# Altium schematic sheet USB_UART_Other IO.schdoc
size 297 x 209 mm; Border: 1; Width: 1170; Height: 825; Region Start: 1; X Region Count: 6; Y Region Count: 4; Blade Width: 10; Title Block Position: 3; Symbol: Sheet-Symbol_A4; Company: 嘉立创EDA; Version: V1.0; Page Size: A4; @Project Name: New Project_2025-01-23_00-40-50; @Page Count: 4; @Update Date: 2025-08-15; @Create Date: 2025-07-30; @Schematic Name: Schematic3_7; @Page No: 1; @Page Name: 继电器板子; Device: Sheet-Symbol_A4; @Board Name: cm4; @Create Time: 15:34:35; @Update Time: 00:10:44
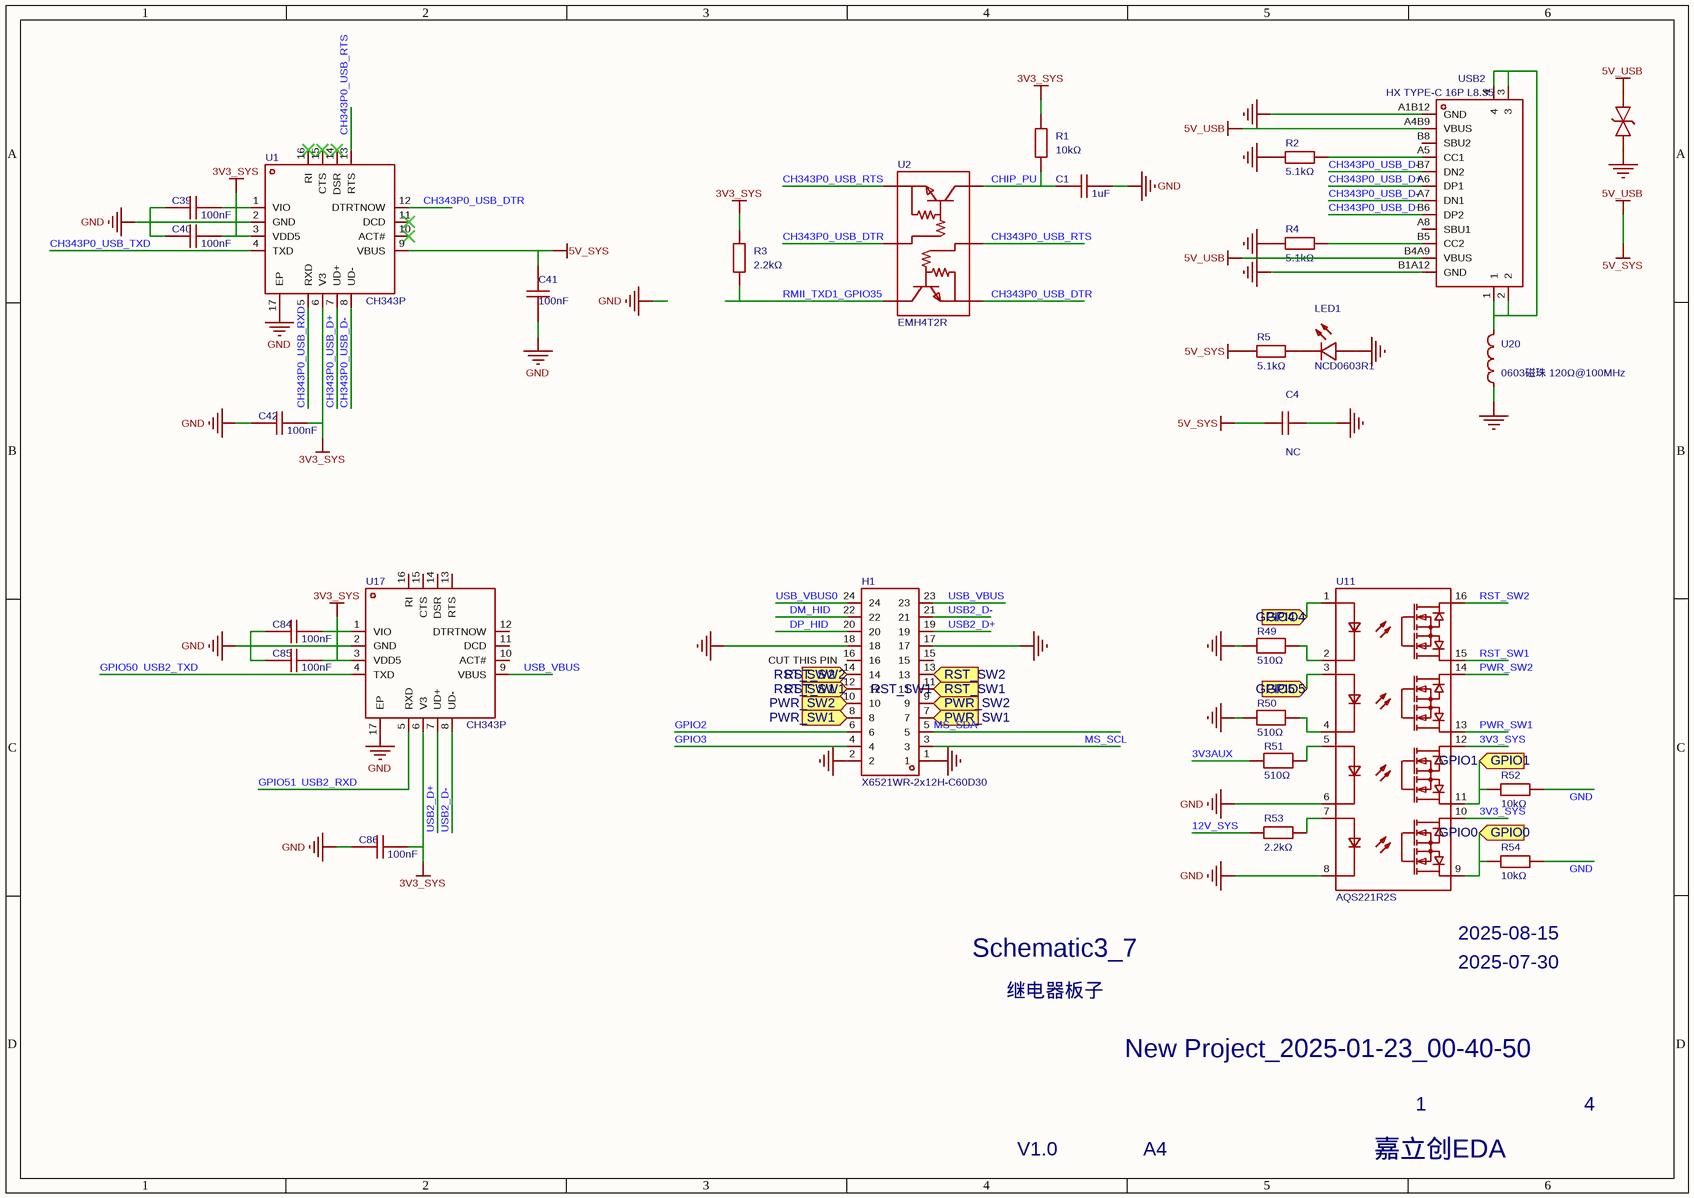
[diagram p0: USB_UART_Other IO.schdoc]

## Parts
C1  1uF  [C0402]
C4  NC  [C0805]
C39  100nF  [C0402 去耦电容]
C40  100nF  [C0402 去耦电容]
C41  100nF  [C0402 去耦电容]
C42  100nF  [C0402 去耦电容]
C84  100nF  [C0402 去耦电容]
C85  100nF  [C0402 去耦电容]
C86  100nF  [C0402 去耦电容]
D1  SLPESD0603M05  [D0603-BI]  (value not drawn)
H1  X6521WR-2x12H-C60D30  [HDR-TH_24P-P2.54-H-M-R2-C12-S2.54]
LED1  NCD0603R1  [LED0603-RD_RED]
R1  10kΩ  [R0402]
R2  5.1kΩ  [R0402]
R3  2.2kΩ  [R0402]
R4  5.1kΩ  [R0402]
R5  5.1kΩ  [R0402]
R49  510Ω  [R0603]
R50  510Ω  [R0603]
R51  510Ω  [R0603]
R52  10kΩ  [R0402]
R53  2.2kΩ  [R0402]
R54  10kΩ  [R0402]
U1  CH343P  [TQFN-16_L3.0-W3.0-P0.50-BL-EP1.7]
U2  EMH4T2R  [SOT-563-6_L1.6-W1.2-P0.50-LS1.6-BL]
U11  AQS221R2S  [SO-16_L10.3-W4.4-P1.27-LS7.0-BL]
U17  CH343P  [TQFN-16_L3.0-W3.0-P0.50-BL-EP1.7]
U20  LCSC Part Name: 0603磁珠 120Ω@100MHz  [L0603]  (hidden comment: BLM18PG121SN1D)
USB2  HX TYPE-C 16P L8.35  [USB-C-SMD_HX-TYPE-C-16P-L8.35]

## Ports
GPIO0 (in), GPIO1 (in), GPIO4 (in), GPIO5 (in), PWR_SW1 (in), PWR_SW2 (in), RST_SW1 (in), RST_SW2 (in)

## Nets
3V3_SYS: C39.2 C40.2 C42.2 C84.2 C85.2 C86.2 R1.1 R3.1 U1.1(VIO) U1.3(VDD5) U1.6(V3) U11.10 U11.12 U17.1(VIO) U17.3(VDD5) U17.6(V3)
5V_SYS: C4.1 C41.2 D1.2 R5.1 U1.9(VBUS) USB2.A4B9(VBUS) USB2.B4A9(VBUS)  [also labelled 5V_USB]
GND: C1.1 C4.2 C39.1 C40.1 C41.1 C42.1 C84.1 C85.1 C86.1 D1.1 H1.1 H1.2 H1.17 H1.18 LED1.2(A) R2.1 R4.1 R49.1 R50.1 R52.1 R54.1 U1.2(GND) U1.17(EP) U11.6 U11.8 U17.2(GND) U17.17(EP) U20.1 USB2.A1B12(GND) USB2.B1A12(GND)
3V3AUX: R51.2
12V_SYS: R53.2
CH343P0_USB_D+: U1.7(UD+) USB2.A6(DP1) USB2.B6(DP2)
CH343P0_USB_D-: U1.8(UD-) USB2.A7(DN1) USB2.B7(DN2)
CH343P0_USB_DTR: U1.12(DTRTNOW) U2.1(E) U2.5(B)
CH343P0_USB_RTS: U1.13(RTS) U2.2(B) U2.4(E)
CH343P0_USB_RXD: U1.5(RXD)
CH343P0_USB_TXD: U1.4(TXD)
CHIP_PU: C1.2 R1.2 U2.3(C)
DM_HID: H1.22
DP_HID: H1.20
GPIO0: R54.2 U11.9 ; port GPIO0
GPIO1: R52.2 U11.11 ; port GPIO1
GPIO2: H1.6
GPIO3: H1.4
GPIO4: U11.1 ; port GPIO4
GPIO5: U11.3 ; port GPIO5
GPIO50: U17.4(TXD)  [also labelled USB2_TXD]
GPIO51: U17.5(RXD)  [also labelled USB2_RXD]
MS_SCL: H1.3
MS_SDA: H1.5
PWR_SW1: U11.13
PWR_SW1: H1.7 H1.8 ; port PWR_SW1  [a separate net that carries the same name]
PWR_SW2: U11.14
PWR_SW2: H1.9 H1.10 ; port PWR_SW2  [a separate net that carries the same name]
RMII_TXD1_GPIO35: R3.2 U2.6(C)
RST_SW1: H1.11 H1.12 U11.15 ; port RST_SW1
RST_SW2: H1.13 H1.14 U11.16 ; port RST_SW2
USB2_D+: H1.19 U17.7(UD+)
USB2_D-: H1.21 U17.8(UD-)
USB_VBUS: H1.23 U17.9(VBUS)
USB_VBUS0: H1.24
NetLED1_1: LED1.1(K) R5.2
NetR2_2: R2.2 USB2.A5(CC1)
NetR4_2: R4.2 USB2.B5(CC2)
NetR49_2: R49.2 U11.2
NetR50_2: R50.2 U11.4
NetR51_1: R51.1 U11.5
NetR53_1: R53.1 U11.7
NetU20_2: U20.2 USB2.1 USB2.2 USB2.3 USB2.4

Not connected (* = marked no-connect by the designer): H1 15 16; U1 10(ACT#)* 11(DCD)* 14(DSR)* 15(CTS)* 16(RI)*; U17 10(ACT#) 11(DCD) 12(DTRTNOW) 13(RTS) 14(DSR) 15(CTS) 16(RI); USB2 A8(SBU1) B8(SBU2)

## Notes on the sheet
- (near H1) CUT THIS PIN

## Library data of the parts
C1 = CL05A105KA5NQNC: 容值:1uF;精度:±10%;额定电压:25V;温度系数:X5R;; Manufacturer: SAMSUNG(三星); Symbol: Capacitance; Add into BOM: yes; 3D Model: 36a51122f27c49738f86b3bfa98863e0; 3D Model Transform: 39.37,19.685,0,0,0,0,0,0,0; Tolerance: ±10%; Voltage Rating: 25V; Temperature Coefficient: X5R; ModelName: C0402_L1.0-W0.5-H0.5
C4 = CL21A475KAQNNNE: 容值:4.7uF;精度:±10%;额定电压:25V;温度系数:X5R;; Manufacturer: SAMSUNG(三星); Check: false; Add into BOM: yes; 3D Model: 1ba041120af144c991958decab20d241; 3D Model Transform: 78.74,51.181,0,0,0,0,0,0.0005,0; Tolerance: ±10%; Temperature Coefficient: X5R; Voltage Rating: 25V; ModelName: C0805_L2.0-W1.3-H1.3
C39-C42 = CL05B104KO5NNNC: 容值:100nF;精度:±10%;额定电压:16V;温度系数:X7R;; Manufacturer: SAMSUNG(三星); Check: false; Add into BOM: yes; Symbol: Capacitance; 3D Model Transform: 39.37,19.685,0,0,0,0,0,0,0; Tolerance: ±10%; Voltage Rating: 16V; Temperature Coefficient: X7R; 3D Model: 36a51122f27c49738f86b3bfa98863e00819f05c4eef4c71ace90d822a990e87; ModelName: C0402_L1.0-W0.5-H0.5
C84-C86 = CL05B104KO5NNNC: 容值:100nF;精度:±10%;额定电压:16V;温度系数:X7R;; Manufacturer: SAMSUNG(三星); Symbol: Capacitance; Add into BOM: yes; 3D Model: 36a51122f27c49738f86b3bfa98863e00819f05c4eef4c71ace90d822a990e87; 3D Model Transform: 39.37,19.685,0,0,0,0,0,0,0; Tolerance: ±10%; Voltage Rating: 16V; Temperature Coefficient: X7R; Check: false; ModelName: C0402_L1.0-W0.5-H0.5
D1 = SLPESD0603M05: 极性:双向;反向截止电压(Vrwm):5V;钳位电压:40V;; Manufacturer: Slkor(萨科微); Add into BOM: yes; 3D Model: a387ce2936f842ebafc868b09fdf8ecc; 3D Model Transform: 62.992,31.496,0,0,0,0,0,0,0; Polarity: 双向; Reverse Stand-Off Voltage (Vrwm): 5V; Clamping Voltage: 40V; Reverse Leakage Current (Ir): 10nA; Number of Channels: 单路; Type: ESD; Junction Capacitance: 0.05pF; ModelName: DO0603_L1.6-W0.8-H0.8-LS1.6
H1 = X6521WR-2x12H-C60D30: 插针结构:2x12P;间距:2.54mm;行距:2.54mm;圆针/方针:方针;排数:双排;总PIN位数:24P;额定电流:3A;额定电压:250V;配合针长度:-;塑高:2.5mm;端接针长度:-;触头材质:黄铜;触头镀层:金;工作温度:-40℃~+105℃;颜色:黑色;; Manufacturer: XKB Connection(中国星坤); Symbol: X6521WR-2×12H-C30D60; AddInBom: yes; ModelId: c87603f207fc4d939d696e0588895b6d0819f05c4eef4c71ace90d822a990e87; ModelName: HDR-TH_24P-P2.54-M-WI-2X12P; ModelTransform: 1199.9976,507.873,0,0,0,0,0,-190.945,-118.11; Pin Structure: 2x12P; Pitch: 2.54mm; Circluar Pins/Square Pins: 方针; Current Rating: 3A; Voltage Rating (Max): 250V
LED1 = NCD0603R1_C84263: 灯头类型:-;发光颜色:红色;正向压降(Vf):1.6V~2.6V;功率:65mW;正向电流:25mA;波长:615nm~630nm;二极管配置:独立二极管;透镜颜色:-;色温:-;发光强度:220mcd;发光角度:130°;载带方式:-;工作温度:-30℃~+85℃;; Manufacturer: 国星光电; Symbol: FC-DA1608HRK-620D; Add into BOM: yes; 3D Model: 74041d3a270d435c8600a9ab9b7641c0; 3D Model Transform: 63.7794,31.496,0,0,0,0,0,-0.002,0; Illumination Color: 红色; Power(Watts): 65mW; Forward Current: 25mA; Peak Wavelength: 630nm; Diode Configuration: 独立二极管; Luminous Intensity: 220mcd; Viewing Angle: 130°
R1 = 0402WGF1002TCE: 电阻类型:厚膜电阻;阻值:10kΩ;精度:±1%;功率:62.5mW;工作电压:50V;温度系数:±100ppm/℃;; Manufacturer: UNI-ROYAL(厚声); Symbol: 电阻; Add into BOM: yes; 3D Model Transform: 39.37,19.685,0,0,0,0,0,0,0; Tolerance: ±1%; Power(Watts): 62.5mW; Voltage-Supply(Max): 50V; 3D Model: 98c88bc2b9094f218f3a3e30a70127380819f05c4eef4c71ace90d822a990e87; ModelName: R0402_L1.0-W0.5-H0.4
R2 R4 R5 = 0402WGF5101TCE: 电阻类型:厚膜电阻;阻值:5.1kΩ;精度:±1%;功率:62.5mW;工作电压:50V;温度系数:±100ppm/℃;; Manufacturer: UNI-ROYAL(厚声); Add into BOM: yes; 3D Model: 98c88bc2b9094f218f3a3e30a7012738; 3D Model Transform: 39.37,19.685,0,0,0,0,0,0,0; Tolerance: ±1%; Power(Watts): 62.5mW; Voltage-Supply(Max): 50V; ModelName: R0402_L1.0-W0.5-H0.4
R3 R53 = 0402WGF2201TCE: 电阻类型:厚膜电阻;阻值:2.2kΩ;精度:±1%;功率:62.5mW;工作电压:50V;温度系数:±100ppm/℃;; Manufacturer: UNI-ROYAL(厚声); Add into BOM: yes; 3D Model: 98c88bc2b9094f218f3a3e30a7012738; 3D Model Transform: 39.37,19.685,0,0,0,0,0,0,0; Tolerance: ±1%; Power(Watts): 62.5mW; Voltage-Supply(Max): 50V; ModelName: R0402_L1.0-W0.5-H0.4
R49-R51 = FRC0603F5100TS: 电阻类型:厚膜电阻;阻值:510Ω;精度:±1%;功率:100mW;工作电压:75V;温度系数:±100ppm/℃;; Manufacturer: FOJAN(富捷); Add into BOM: yes; 3D Model: fc143cca1e79419f9cd78b61e9279f08; 3D Model Transform: 31.8897,63.7794,0,90,0,0,0,0,0; Tolerance: ±1%; Power(Watts): 100mW; Voltage-Supply(Max): 75V
R52 R54 = 0402WGF1002TCE: 电阻类型:厚膜电阻;阻值:10kΩ;精度:±1%;功率:62.5mW;工作电压:50V;温度系数:±100ppm/℃;; Manufacturer: UNI-ROYAL(厚声); Add into BOM: yes; 3D Model: 98c88bc2b9094f218f3a3e30a7012738; 3D Model Transform: 39.37,19.685,0,0,0,0,0,0,0; Tolerance: ±1%; Power(Watts): 62.5mW; Voltage-Supply(Max): 50V; ModelName: R0402_L1.0-W0.5-H0.4
U1 = CH343P: 应用功能:USB转UART;USB协议版本:USB 2.0;通道数:-;数据速率:6Mbps;; Manufacturer: WCH(南京沁恒); AddInBom: yes; ModelId: bf3177fc8dab4136825cc9ae9b354cf20819f05c4eef4c71ace90d822a990e87; ModelTransform: 118.8974,118.8974,0,0,0,0,0,0,0; USB Protocol: USB 2.0; Voltage - Supply: 3.3V；5V; Data Rate: 6Mbps; Current - Supply: 3mA; Supply Current (Iq): 90uA
U2 = EMH4T2R: 数量:2个NPN-预偏置;集射极击穿电压(Vceo):50V;集电极电流(Ic):100mA;耗散功率(Pd):150mW;直流电流增益(hFE):600;; Manufacturer: ROHM(罗姆); AddInBom: yes; ModelId: 03ffed36a9f44d3f8e9b9d03c9339c510819f05c4eef4c71ace90d822a990e87; ModelTransform: 62.992,62.992,0,0,0,0,0,0,0; Collector - Emitter Voltage VCEO: 50V; Current - Collector(Ic): 100mA; Pd - Power Dissipation: 150mW; DC Current Gain: 600; Emitter-Base Voltage VEBO: 5V; Input Resistor: 13kΩ; Vce Saturation(VCE(sat)): 300mV; Transition frequency(fT): 250MHz; Current - Collector Cutoff: 500nA
U11 = AQS221R2S: Manufacturer: PANASONIC(松下); 3D Model: 3466bc42bba0413d8ed37ce37c1ae1480819f05c4eef4c71ace90d822a990e87; 3D Model Transform: 275.824,405.511,0,90,0,0,0,0,0; AddInBom: yes; ModelName: SO-16_L10.3-W4.4-H2.1-P1.27
U17 = CH343P: 应用功能:USB转UART;USB协议版本:USB 2.0;通道数:-;数据速率:6Mbps;; Manufacturer: WCH(南京沁恒); 3D Model: bf3177fc8dab4136825cc9ae9b354cf20819f05c4eef4c71ace90d822a990e87; 3D Model Transform: 118.8974,118.8974,0,0,0,0,0,0,0; USB Protocol: USB 2.0; Voltage - Supply: 3.3V；5V; Data Rate: 6Mbps; Current - Supply: 3mA; Supply Current (Iq): 90uA; AddInBom: yes
U20 = BLM18PG121SN1D: 标称阻抗@测试频率:120Ω@100MHz;误差:±25%;直流电阻(RDC):50mΩ;; Manufacturer: muRata(村田); Symbol: BLM18PG121SN1D_C14709; 3D Model: 2bc5ec593d464d6ba9807aec0b5673c2; 3D Model Transform: 62.992,31.496,0,180,0,0,0.094,0.629,0; Tolerance: ±25%; DC Resistance: 50mΩ; Current Rating: 2A; Circuits: 1; AddInBom: yes; ModelName: L0603_L1.6-W0.8-H0.5_BEAD
USB2 = HX TYPE-C 16P L8.35: 连接器类型:Type-C;协议标准:USB 3.1;公母:母;安装方式:卧贴;触点数量:16P;端口数量:1;额定电流 - 电源:3A;工作温度:-30℃~+80℃;; Manufacturer: hanxia(韩下); AddInBom: yes; ModelId: f0568753507b47a9986749ff543c37600819f05c4eef4c71ace90d822a990e87; ModelTransform: 351.9678,354.33,0,0,0,0,-0.004,-62.993,-33.465; Protocol Standard: USB 3.1; Gender: 母; Number of Ports: 1; Current Rating-Power: 3A; Voltage Rating: 20V; Connect-Disconnect Life: 5千次; Center Height: 1.68mm; Detection color: 黑色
